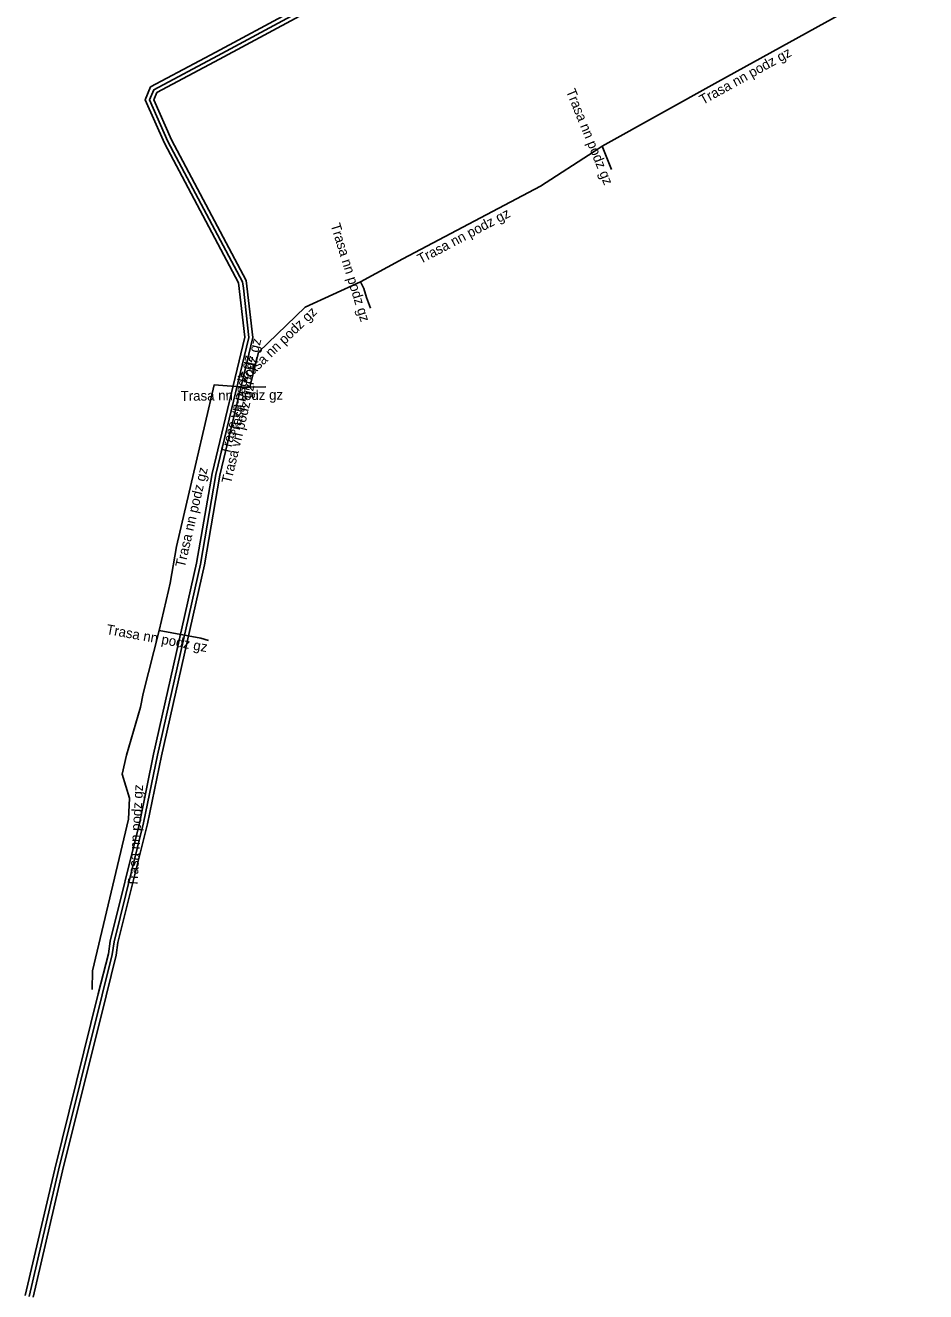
# Model space of a CAD drawing. Extents: x -687924 to -686708, y -1056742 to -1056249.
# Drawn here: x -687476.6 to -687431.2, y -1056578.1 to -1056514.3 of the extents above; entities that cross this region are included whole.
import ezdxf

# ---------------------------------------------------------------- set-up
doc = ezdxf.new("R2010")
doc.units = 0
for name, color, linetype in [('Popiskový text - Ostatní atributy Trasy', 7, 'Continuous'), ('Spojnice NN', 7, 'Continuous'), ('Spojnice VN', 7, 'Continuous')]:
    doc.layers.add(name, color=color, linetype=linetype)

msp = doc.modelspace()

# ---------------------------------------------------------------- linework, layer by layer
at = {"layer": 'Spojnice NN'}
for points in [[(-687431.2, -1056511.26), (-687434.49, -1056513.15), (-687441.68, -1056517.13), (-687447.52, -1056520.36)], [(-687447.52, -1056520.36), (-687447.91, -1056520.64), (-687450.62, -1056522.39), (-687457.56, -1056526.05), (-687459.71, -1056527.21)], [(-687447.52, -1056520.36), (-687447.04, -1056521.54)], [(-687459.71, -1056527.21), (-687462.5, -1056528.49), (-687464.84, -1056530.75), (-687465.29, -1056532.52)], [(-687459.71, -1056527.21), (-687459.54, -1056527.54), (-687459.4, -1056527.99), (-687459.2, -1056528.53)], [(-687465.29, -1056532.52), (-687465.56, -1056532.52), (-687467.08, -1056532.4), (-687467.99, -1056536.3), (-687468.98, -1056540.56), (-687469.3, -1056542.4), (-687469.39, -1056542.77), (-687469.85, -1056544.79)], [(-687465.29, -1056532.52), (-687464.48, -1056532.51)], [(-687469.85, -1056544.79), (-687470.66, -1056547.96), (-687470.79, -1056548.65), (-687471.5, -1056551.07), (-687471.72, -1056552.04), (-687471.35, -1056553.24), (-687471.41, -1056554.3), (-687473.22, -1056561.95), (-687473.24, -1056562.9)], [(-687469.85, -1056544.79), (-687467.75, -1056545.17), (-687467.37, -1056545.29)]]:
    msp.add_lwpolyline(points, dxfattribs=at)
at = {"layer": 'Spojnice VN'}
for points in [[(-687459.366, -1056511.505), (-687467.004, -1056515.634), (-687470.287, -1056517.377), (-687470.557, -1056518.033), (-687469.59, -1056520.217), (-687465.853, -1056527.264), (-687465.543, -1056529.997), (-687467.186, -1056536.88), (-687467.966, -1056541.401), (-687470.136, -1056551.028), (-687470.835, -1056554.446), (-687472.327, -1056560.452), (-687472.417, -1056561.092), (-687472.924, -1056563.111), (-687475.124, -1056571.953), (-687476.605, -1056578.325)], [(-687476.41, -1056578.37), (-687474.93, -1056572), (-687472.73, -1056563.16), (-687472.22, -1056561.13), (-687472.13, -1056560.49), (-687470.64, -1056554.49), (-687469.94, -1056551.07), (-687467.77, -1056541.44), (-687466.99, -1056536.92), (-687465.34, -1056530.01), (-687465.61, -1056527.53), (-687465.66, -1056527.2), (-687469.41, -1056520.13), (-687470.34, -1056518.03), (-687470.13, -1056517.52), (-687466.91, -1056515.81), (-687459.27, -1056511.68)], [(-687476.215, -1056578.415), (-687474.736, -1056572.047), (-687472.536, -1056563.209), (-687472.023, -1056561.168), (-687471.933, -1056560.528), (-687470.445, -1056554.534), (-687469.744, -1056551.112), (-687467.574, -1056541.479), (-687466.794, -1056536.96), (-687465.137, -1056530.023), (-687465.467, -1056527.136), (-687469.23, -1056520.043), (-687470.123, -1056518.027), (-687469.973, -1056517.663), (-687466.816, -1056515.986), (-687459.174, -1056511.855)]]:
    msp.add_lwpolyline(points, dxfattribs=at)

# ---------------------------------------------------------------- texts
at = {"layer": 'Popiskový text - Ostatní atributy Trasy'}
for s, rotation, p in [('Trasa nn podz gz', 28.96657, (-687442.437, -1056518.291)), ('Trasa nn podz gz', 292.13549, (-687449.35, -1056517.588)), ('Trasa nn podz gz', 27.80616, (-687456.672, -1056526.316)), ('Trasa nn podz gz', 287.2815, (-687461.217, -1056524.338)), ('Trasa nn podz gz', 44.00365, (-687465.572, -1056532.361)), ('Trasa vn podz gz', 76.57014, (-687465.889, -1056535.107)), ('Trasa vn podz gz', 76.5745, (-687466.298, -1056535.959)), ('Trasa nn podz gz', 0.70732, (-687468.77, -1056533.213)), ('Trasa vn podz gz', 76.56582, (-687466.234, -1056537.413)), ('Trasa nn podz gz', 76.91701, (-687468.566, -1056541.649)), ('Trasa nn podz gz', 349.74318, (-687472.551, -1056544.962)), ('Trasa nn podz gz', 86.7603, (-687470.952, -1056557.727))]:
    msp.add_text(s, height=0.5, rotation=rotation, dxfattribs=at).set_placement(p)

doc.saveas('drawing.dxf')
